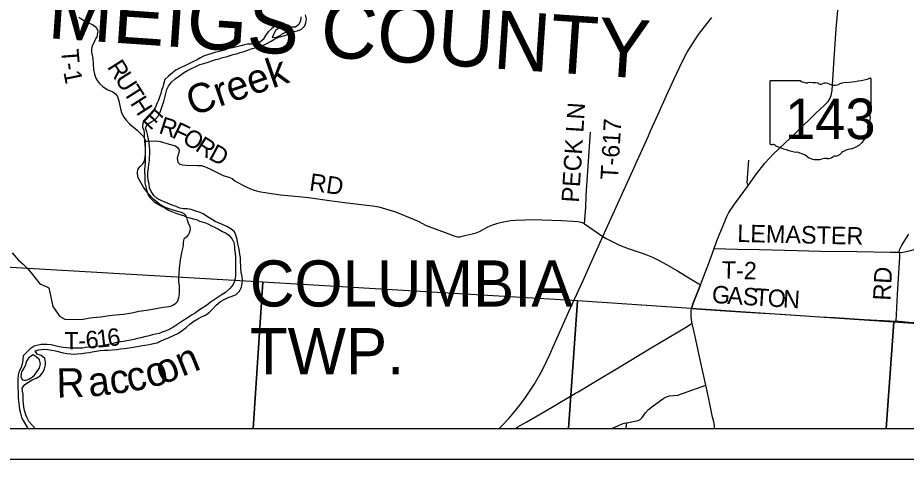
# Model space of a CAD drawing. Extents: x 0 to 34, y 0 to 22.
# Drawn here: x 4.418 to 7.302, y 14 to 15.435 of the extents above; entities that cross this region are included whole.
import ezdxf

# ---------------------------------------------------------------- set-up
doc = ezdxf.new("R2010")
doc.units = 0
for name, color, linetype in [('GM_X_Corporation', 7, 'Continuous'), ('GM_X_County_Road', 7, 'Continuous'), ('GM_X_County_Text', 7, 'Continuous'), ('GM_X_Major_River', 7, 'Continuous'), ('GM_X_Major_River_Text', 7, 'Continuous'), ('GM_X_State_Location', 7, 'Continuous'), ('GM_X_State_Route', 7, 'Continuous'), ('GM_X_State_Shield', 7, 'Continuous'), ('GM_X_Township_Road', 7, 'Continuous'), ('GM_X_Township_Road_Text', 7, 'Continuous'), ('GM_X_Township_Text', 7, 'Continuous'), ('SH_Data', 7, 'Continuous')]:
    doc.layers.add(name, color=color, linetype=linetype)

msp = doc.modelspace()

# ---------------------------------------------------------------- linework, layer by layer
at = {"layer": 'GM_X_Corporation'}
for points in [[(4.1481, 14.1), (8.9, 14.1), (8.9, 15.3662), (8.5054, 15.3919), (7.8479, 15.4342), (7.082, 15.4841), (6.7558, 15.5053), (6.7389, 15.5063), (6.2987, 15.5286), (5.4088, 15.5882), (4.4836, 15.6492), (4.4152, 15.6505), (4.2922, 15.6568), (4.2674, 15.6579), (4.2558, 15.6584), (4.2352, 15.4905), (4.2113, 15.0848), (4.1846, 14.6877), (4.1741, 14.5315), (4.1604, 14.3288)], [(4.1538, 14.1), (5.1819, 14.1), (5.2132, 14.5759), (4.1896, 14.6347)], [(5.1819, 14.1), (6.2054, 14.1), (6.2355, 14.5152), (5.2132, 14.5759)], [(6.2054, 14.1), (7.2372, 14.1), (7.2616, 14.4454), (6.2355, 14.5152)], [(7.2372, 14.1), (8.2568, 14.1), (8.2775, 14.3752), (7.2616, 14.4454)]]:
    msp.add_lwpolyline(points, close=True, dxfattribs=at)
at = {"layer": 'GM_X_County_Road'}
for points in [[(6.07, 14.1218), (6.1511, 14.1685), (6.2289, 14.2147), (6.2374, 14.2193), (6.2996, 14.2571), (6.3617, 14.2938), (6.4745, 14.3616), (6.5914, 14.4312), (6.6022, 14.4387), (6.6074, 14.4407)], [(6.0341, 14.1), (6.0414, 14.1051), (6.0562, 14.1139), (6.07, 14.1218)]]:
    msp.add_lwpolyline(points, dxfattribs=at)
at = {"layer": 'GM_X_Major_River'}
for points in [[(5.337, 15.4377), (5.3359, 15.4245), (5.3303, 15.4127), (5.319, 15.404), (5.3053, 15.4043), (5.294, 15.4103), (5.2807, 15.4141), (5.2674, 15.414), (5.2557, 15.4091), (5.2421, 15.4003), (5.2312, 15.3889), (5.2225, 15.3771), (5.2149, 15.3642), (5.2028, 15.354), (5.1904, 15.3513), (5.1767, 15.3493), (5.1639, 15.3485), (5.154, 15.3466), (5.1423, 15.3435), (5.1291, 15.3405), (5.1151, 15.3374), (5.1026, 15.3347), (5.0909, 15.3305), (5.0803, 15.3274), (5.0674, 15.3236), (5.0576, 15.3217), (5.0212, 15.3095), (5.0107, 15.3049), (4.9997, 15.2984), (4.9857, 15.2919), (4.971, 15.2839), (4.96, 15.2786), (4.9445, 15.2717), (4.9313, 15.2641), (4.9203, 15.2557), (4.9074, 15.2447), (4.8957, 15.2337), (4.8908, 15.2189), (4.8882, 15.2094), (4.8848, 15.1995), (4.8822, 15.1889), (4.8788, 15.1794), (4.8743, 15.1672), (4.8702, 15.1578), (4.8645, 15.1441), (4.8577, 15.1323), (4.8479, 15.1186), (4.8351, 15.1065), (4.8237, 15.0932), (4.8226, 15.0795), (4.8268, 15.0693), (4.8276, 15.0594), (4.828, 15.0466), (4.8292, 15.0337), (4.8307, 15.0212), (4.8311, 15.0113), (4.8311, 14.9988), (4.8315, 14.9863), (4.8316, 14.9658), (4.8301, 14.951), (4.829, 14.9415), (4.8294, 14.9321), (4.8302, 14.9222), (4.8298, 14.9082), (4.8306, 14.8987), (4.8333, 14.8854), (4.8363, 14.8722), (4.8409, 14.8593), (4.8481, 14.8495), (4.8606, 14.8366), (4.8732, 14.8287), (4.8868, 14.8211), (4.8985, 14.8143), (4.9092, 14.8087), (4.9201, 14.8038), (4.9308, 14.7997), (4.9436, 14.7948), (4.9554, 14.7918), (4.9667, 14.7872), (4.9766, 14.7846), (4.9876, 14.7816), (4.9978, 14.7786), (5.0077, 14.7741), (5.0236, 14.7688), (5.0345, 14.7647), (5.0467, 14.759), (5.0569, 14.7538), (5.0694, 14.7474)], [(5.1213, 14.7395), (5.1095, 14.749), (5.097, 14.7558), (5.0849, 14.7614), (5.0584, 14.7727), (5.0463, 14.7806), (5.0334, 14.7882), (5.0201, 14.7973), (5.0102, 14.8014), (4.9962, 14.8063), (4.9807, 14.8112), (4.9674, 14.8134), (4.9557, 14.8138), (4.9443, 14.8156), (4.9322, 14.8209), (4.9193, 14.8254), (4.9065, 14.8307), (4.8928, 14.8367), (4.8833, 14.8408), (4.8708, 14.8476), (4.8591, 14.8567), (4.8503, 14.8699), (4.8458, 14.8817), (4.8439, 14.8946), (4.8408, 14.9067), (4.8396, 14.9196), (4.84, 14.9313), (4.8419, 14.9465), (4.8433, 14.9575), (4.8452, 14.9708), (4.8456, 14.9821), (4.8463, 14.9928), (4.8466, 15.003), (4.8459, 15.0159), (4.8447, 15.0288), (4.8401, 15.0515), (4.8367, 15.0644), (4.8329, 15.0769), (4.8389, 15.0894), (4.851, 15.0963), (4.8627, 15.1031), (4.8737, 15.1153), (4.8804, 15.1282), (4.8838, 15.1377), (4.888, 15.1506), (4.8917, 15.1624), (4.8981, 15.1882), (4.9015, 15.2014), (4.9071, 15.2125), (4.9166, 15.225), (4.9287, 15.236), (4.9423, 15.2459), (4.9555, 15.2554), (4.9687, 15.2631), (4.9823, 15.2703), (4.9963, 15.2768), (5.0088, 15.2825), (5.0217, 15.2863), (5.036, 15.2905), (5.0474, 15.2947), (5.061, 15.299), (5.0712, 15.3016), (5.0826, 15.3051), (5.0947, 15.3078), (5.1045, 15.3105), (5.1166, 15.315), (5.1276, 15.3177), (5.1401, 15.3215), (5.1526, 15.325), (5.1647, 15.3292), (5.176, 15.3334), (5.1881, 15.3369), (5.2006, 15.3411), (5.215, 15.3453), (5.2267, 15.3506), (5.2403, 15.3582), (5.2524, 15.3662), (5.2649, 15.3712), (5.277, 15.3746), (5.2883, 15.3785), (5.3012, 15.3838), (5.3137, 15.3899), (5.3258, 15.3922), (5.3387, 15.3972), (5.3492, 15.4086), (5.353, 15.4181), (5.3549, 15.4314), (5.3522, 15.4439)], [(5.2974, 15.3952), (5.2906, 15.3974), (5.2822, 15.4001), (5.2747, 15.4019), (5.2686, 15.4015), (5.2622, 15.3989), (5.2558, 15.3939), (5.2509, 15.3863), (5.2478, 15.3802), (5.2433, 15.37)], [(5.2433, 15.37), (5.2577, 15.3712), (5.2645, 15.3746), (5.2713, 15.3784), (5.2777, 15.3834), (5.2838, 15.386), (5.2883, 15.3883), (5.2932, 15.3906), (5.2974, 15.3952)], [(5.0694, 14.7474), (5.0823, 14.7406), (5.094, 14.7342), (5.1035, 14.7281), (5.1142, 14.7153), (5.1187, 14.7039), (5.121, 14.691), (5.1218, 14.6815), (5.123, 14.6694), (5.1241, 14.6558), (5.1245, 14.6448), (5.1249, 14.6311), (5.125, 14.5955), (5.1224, 14.5811), (5.1167, 14.5682), (5.1062, 14.5549), (5.0922, 14.5423), (5.0816, 14.5358), (5.0555, 14.5183), (5.0427, 14.5092), (5.0302, 14.4993), (5.0166, 14.4905), (5.0049, 14.4829), (4.9935, 14.4742), (4.9822, 14.4677), (4.9675, 14.4586), (4.9535, 14.4498), (4.9436, 14.443), (4.9312, 14.4346), (4.9213, 14.4285), (4.9066, 14.4209), (4.8964, 14.4163), (4.8862, 14.4128), (4.8763, 14.4083), (4.865, 14.4063), (4.8548, 14.404), (4.84, 14.3998), (4.829, 14.3975), (4.8169, 14.3948), (4.8063, 14.3925), (4.795, 14.3895), (4.7844, 14.3872), (4.7723, 14.3845), (4.7609, 14.3822), (4.7511, 14.381), (4.7382, 14.3791), (4.7273, 14.3764), (4.7114, 14.3725), (4.7008, 14.3702), (4.6909, 14.3687), (4.6803, 14.3671), (4.6667, 14.366), (4.6527, 14.3644), (4.6376, 14.3636), (4.6277, 14.3613), (4.6141, 14.3605), (4.6016, 14.3605), (4.5884, 14.3608), (4.5755, 14.3615), (4.5653, 14.3626), (4.5524, 14.3656), (4.5391, 14.3686), (4.5263, 14.3716), (4.5134, 14.3727), (4.4937, 14.3727), (4.4835, 14.3707), (4.4706, 14.3677), (4.4578, 14.3593), (4.4472, 14.3479), (4.4351, 14.3365), (4.4336, 14.3225), (4.4321, 14.3088), (4.4291, 14.2986), (4.422, 14.2857), (4.4186, 14.2731), (4.4179, 14.2606), (4.4183, 14.2511), (4.4183, 14.2295), (4.4187, 14.2182), (4.4195, 14.2087), (4.4195, 14.1992), (4.4199, 14.1897), (4.4218, 14.1731), (4.4234, 14.1617), (4.4261, 14.1496), (4.4303, 14.1359), (4.4348, 14.1261), (4.4432, 14.1125), (4.4489, 14.1022), (4.4506, 14.1)], [(4.4747, 14.1), (4.4746, 14.1), (4.4651, 14.1091), (4.4549, 14.1212), (4.4477, 14.1345), (4.4439, 14.1447), (4.4393, 14.1587), (4.4378, 14.1693), (4.4362, 14.1811), (4.4354, 14.1905), (4.4354, 14.2106), (4.4335, 14.2212), (4.4316, 14.2311), (4.4406, 14.2425), (4.4527, 14.2509), (4.4648, 14.2577), (4.4777, 14.2631), (4.4901, 14.2714), (4.5, 14.2844), (4.5045, 14.2939), (4.5075, 14.3067), (4.5082, 14.317), (4.5055, 14.3276), (4.4938, 14.337), (4.4809, 14.3412), (4.4744, 14.3518), (4.4866, 14.356), (4.5009, 14.3572), (4.5157, 14.3561), (4.5282, 14.3546), (4.5399, 14.3523), (4.5649, 14.3463), (4.5771, 14.3441), (4.5892, 14.343), (4.6001, 14.3419), (4.6107, 14.3427), (4.6255, 14.3435), (4.6387, 14.3462), (4.6497, 14.3473), (4.6596, 14.3485), (4.6717, 14.3512), (4.6853, 14.3531), (4.6982, 14.3543), (4.7114, 14.3547), (4.725, 14.3551), (4.7379, 14.3567), (4.7511, 14.3586), (4.7636, 14.3598), (4.7788, 14.3621), (4.792, 14.364), (4.8053, 14.3664), (4.8159, 14.3687), (4.8446, 14.3733), (4.8579, 14.376), (4.8707, 14.3783), (4.8809, 14.3836), (4.8949, 14.3897), (4.9048, 14.3939), (4.9252, 14.4031), (4.9392, 14.41), (4.952, 14.4183), (4.9641, 14.4282), (4.9762, 14.4389), (4.9891, 14.4484), (5.0027, 14.4568), (5.0144, 14.4629), (5.0272, 14.4682), (5.0401, 14.4781), (5.0514, 14.4887), (5.062, 14.5009), (5.0764, 14.5123), (5.0881, 14.5196), (5.1013, 14.5253), (5.1138, 14.5299), (5.127, 14.5352), (5.1376, 14.5459), (5.1444, 14.5588), (5.1466, 14.5717), (5.147, 14.5811), (5.1458, 14.5937), (5.1428, 14.6077), (5.1424, 14.6206), (5.142, 14.63), (5.1408, 14.6403), (5.1404, 14.6554), (5.1392, 14.6657), (5.1377, 14.6759), (5.1358, 14.6869), (5.1327, 14.6998), (5.1301, 14.7145), (5.1262, 14.7282), (5.1213, 14.7395)], [(4.4673, 14.3396), (4.459, 14.3343), (4.4541, 14.329), (4.4503, 14.3248), (4.4458, 14.3187), (4.4439, 14.3115), (4.4424, 14.3058), (4.4379, 14.2959), (4.4303, 14.2842), (4.4284, 14.2773), (4.4277, 14.2682), (4.433, 14.2576)], [(4.433, 14.2576), (4.4379, 14.2565), (4.4444, 14.2573), (4.4478, 14.2581), (4.4531, 14.26), (4.4595, 14.2634), (4.4659, 14.268), (4.472, 14.2729), (4.4791, 14.2839), (4.4852, 14.2915), (4.4886, 14.2968), (4.4908, 14.3052), (4.4912, 14.3097), (4.4885, 14.323), (4.4862, 14.3253), (4.4779, 14.3328), (4.4673, 14.3396)]]:
    msp.add_lwpolyline(points, dxfattribs=at)
at = {"layer": 'GM_X_State_Route'}
for points in [[(6.7476, 14.8327), (6.7629, 14.8542), (6.7898, 14.8906), (6.8166, 14.9278), (6.8432, 14.9619), (6.8591, 14.9796), (6.8687, 14.9898), (6.9461, 15.0631), (7.0087, 15.1251), (7.0358, 15.1494), (7.0486, 15.1622), (7.0541, 15.1711), (7.0585, 15.1816), (7.0614, 15.1978), (7.0661, 15.269), (7.075, 15.3988), (7.0822, 15.4835)], [(5.9804, 14.1), (5.9868, 14.1059), (6.0116, 14.1319), (6.0284, 14.1515), (6.0478, 14.1752), (6.0665, 14.2006), (6.0945, 14.2428), (6.1109, 14.2714), (6.1231, 14.2951), (6.1436, 14.3381), (6.1599, 14.3752), (6.2073, 14.4799), (6.2193, 14.5056), (6.2529, 14.581), (6.2781, 14.6369), (6.317, 14.7235), (6.3386, 14.7712), (6.4078, 14.9242), (6.4654, 15.0513), (6.4725, 15.067), (6.497, 15.1215), (6.5242, 15.1824), (6.5487, 15.2367), (6.5758, 15.2937), (6.5915, 15.3226), (6.6079, 15.3497), (6.6281, 15.3803), (6.643, 15.3998), (6.6546, 15.4153), (6.671, 15.4354)], [(6.6348, 14.5669), (6.6615, 14.6369), (6.679, 14.6849), (6.6879, 14.7099), (6.7154, 14.7784), (6.7197, 14.7892), (6.7267, 14.8014), (6.7424, 14.8253), (6.7476, 14.8327)], [(6.6057, 14.4895), (6.6111, 14.5072), (6.6325, 14.5615), (6.6348, 14.5669)], [(6.6801, 14.1), (6.6797, 14.1091), (6.6778, 14.1213), (6.6738, 14.1372), (6.6611, 14.1966), (6.6515, 14.2403), (6.6354, 14.3134), (6.6166, 14.3991), (6.6074, 14.4407), (6.6057, 14.4527), (6.6041, 14.4649), (6.6041, 14.4748), (6.6043, 14.4822), (6.6057, 14.4895)]]:
    msp.add_lwpolyline(points, dxfattribs=at)
at = {"layer": 'GM_X_State_Shield'}
for p, q in [((7.1888, 15.13), (7.1888, 15.2347)), ((6.8592, 15.2263), (6.8592, 15.0262)), ((6.959, 15.2297), (6.8625, 15.2297)), ((7.1888, 15.13), (7.1888, 15.13))]:
    msp.add_line(p, q, dxfattribs=at)
for centre, major_axis, start_param, end_param in [((7.0714, 15.5026), (0.3495, 0), 4.814394, 5.042369), ((7.1851, 15.2351), (0.00367, 0), 6.141152, 7.989035), ((6.863, 15.2267), (0.00382, 0), 1.712693, 3.28349), ((6.982, 15.253), (0.037, 0), 4.042523, 4.731795), ((6.9942, 15.1174), (0.133, 0), 1.404758, 1.657858), ((7.0244, 15.2278), (0.0107, 0), 3.836095, 5.185415), ((7.0401, 15.2046), (0.0222, 0), 0.950623, 2.079405), ((7.0688, 15.2364), (0.0267, 0), 4.081561, 5.145723), ((7.116, 15.1686), (0.0703, 0), 1.699011, 2.107814), ((7.188, 15.1223), (0.00568, 0), 1.883978, 3.671073), ((7.1518, 15.1091), (0.0341, 0), 5.934695, 6.695948), ((7.1849, 15.1296), (0.00393, 0), 5.05454, 6.418171), ((7.2019, 15.0862), (0.0248, 0), 2.387724, 3.262537), ((7.091, 15.0729), (0.0874, 0), 5.101752, 6.440018), ((6.863, 15.0257), (0.00385, 0), 3.00124, 4.508301), ((6.8636, 15.0462), (0.0294, 0), 4.665946, 4.897461), ((6.8696, 15.0146), (0.0106, 0), 0.519207, 1.627899), ((7.0034, 15.1944), (0.2524, 0), 4.195997, 4.488961), ((7.1278, 14.97), (0.0479, 0), 1.647645, 2.488434), ((6.9282, 14.9363), (0.079, 0), 0.823519, 1.323587), ((7.0136, 15.0136), (0.0501, 0), 4.026481, 4.996735), ((7.0426, 14.9444), (0.0412, 0), 1.495662, 1.94098), ((7.0462, 14.9987), (0.0267, 0), 4.691044, 5.507374), ((7.0704, 14.9793), (0.00752, 0), 1.147584, 2.315152), ((7.0672, 15.0068), (0.0282, 0), 4.937069, 5.64225)]:
    msp.add_ellipse(centre, major_axis=major_axis, ratio=0.8, start_param=start_param, end_param=end_param, dxfattribs=at)
at = {"layer": 'GM_X_Township_Road'}
msp.add_line((6.2573, 14.7653), (6.317, 14.7235), dxfattribs=at)
for points in [[(4.6157, 15.4371), (4.6259, 15.4299), (4.6346, 15.4242), (4.6443, 15.4193), (4.6602, 15.4129), (4.6695, 15.4062), (4.6745, 15.4), (4.6775, 15.3926), (4.6769, 15.3856), (4.6755, 15.3783), (4.6739, 15.3732), (4.6706, 15.366), (4.6663, 15.3578), (4.66, 15.3455), (4.6579, 15.3388), (4.6566, 15.332), (4.6568, 15.3241), (4.6586, 15.3174), (4.6619, 15.3019), (4.663, 15.2854), (4.6635, 15.2669), (4.6669, 15.2519), (4.6716, 15.2379), (4.6762, 15.2295), (4.6831, 15.2206), (4.6934, 15.2114), (4.7082, 15.2017), (4.7259, 15.194), (4.735, 15.1872), (4.7412, 15.1788), (4.744, 15.1715), (4.7458, 15.1643), (4.7481, 15.1537), (4.752, 15.1348), (4.7541, 15.1267), (4.7578, 15.1189), (4.7621, 15.1115), (4.7695, 15.1021), (4.7804, 15.0903), (4.8053, 15.0689), (4.8164, 15.0585), (4.8246, 15.0502), (4.8274, 15.0467), (4.8288, 15.0426), (4.8325, 15.0341), (4.8398, 15.0339), (4.868, 15.0345), (4.8795, 15.0326), (4.9091, 15.0243), (4.9299, 15.0183), (4.9367, 15.0135), (4.9401, 15.0078), (4.9414, 15.0019), (4.9411, 14.9968), (4.9387, 14.9891), (4.9353, 14.9781), (4.9358, 14.9703), (4.9376, 14.9655), (4.9404, 14.9621), (4.9444, 14.9593), (4.9523, 14.9566), (4.9636, 14.9556), (5.0024, 14.9549), (5.014, 14.9546), (5.0245, 14.9515), (5.0439, 14.943), (5.0609, 14.9339), (5.0739, 14.9273), (5.0848, 14.9226), (5.1034, 14.9168), (5.1136, 14.9118), (5.1229, 14.9045), (5.1466, 14.8917), (5.1616, 14.8846), (5.173, 14.879), (5.1857, 14.8742), (5.2003, 14.8702), (5.2269, 14.8655), (5.2708, 14.8597), (5.3062, 14.8557), (5.3613, 14.8509), (5.4293, 14.8406), (5.479, 14.8341), (5.5515, 14.8261), (5.5709, 14.8237), (5.5904, 14.82), (5.6121, 14.8137), (5.6445, 14.8039), (5.6733, 14.7924), (5.7182, 14.7732), (5.744, 14.7597), (5.8058, 14.7371), (5.8364, 14.7249), (5.8454, 14.723), (5.8516, 14.7229), (5.874, 14.7284), (5.8927, 14.732), (5.906, 14.7354), (5.9173, 14.7406), (5.9436, 14.755), (5.9597, 14.762), (5.9759, 14.7676), (5.9953, 14.7719), (6.0187, 14.7754), (6.034, 14.7767), (6.0649, 14.7784), (6.0864, 14.7793), (6.1837, 14.7757), (6.2197, 14.7739), (6.236, 14.7729), (6.2419, 14.7716), (6.2464, 14.7705), (6.2501, 14.7688), (6.2573, 14.7653)], [(6.2573, 14.7653), (6.2616, 14.8192), (6.2637, 14.8573), (6.2702, 14.9529), (6.2769, 15.0629)], [(4.5489, 14.4713), (4.5531, 14.4649), (4.5704, 14.4554), (4.6245, 14.4544), (4.6519, 14.459), (4.6729, 14.4616), (4.6874, 14.4624), (4.708, 14.4659), (4.7241, 14.4682), (4.7476, 14.4699), (4.7608, 14.4712), (4.7882, 14.4758), (4.8106, 14.4807), (4.8355, 14.4842), (4.8555, 14.4874), (4.8894, 14.4938), (4.9088, 14.4966), (4.9169, 14.4987), (4.9233, 14.5017), (4.9311, 14.5067), (4.9358, 14.5125), (4.939, 14.519), (4.9409, 14.525), (4.9425, 14.537), (4.9432, 14.5512), (4.9425, 14.5642), (4.9409, 14.5761), (4.9402, 14.5883), (4.9413, 14.6043), (4.9427, 14.6197), (4.9461, 14.6476), (4.9507, 14.6709), (4.9508, 14.6716), (4.9544, 14.6893), (4.9554, 14.6981), (4.9558, 14.7046), (4.9567, 14.7106), (4.9575, 14.7149), (4.9595, 14.7182), (4.9635, 14.7214), (4.9685, 14.7248), (4.9718, 14.7294), (4.9756, 14.7359), (4.9778, 14.7435), (4.9786, 14.7488), (4.9775, 14.7553), (4.9724, 14.7668), (4.9687, 14.7774), (4.9669, 14.7855), (4.9635, 14.7919), (4.9581, 14.7973), (4.9491, 14.8021), (4.9258, 14.8083), (4.8993, 14.8171), (4.8791, 14.8282), (4.8599, 14.8441), (4.8415, 14.8632), (4.8258, 14.884), (4.8127, 14.9074), (4.809, 14.9149), (4.8074, 14.922), (4.8064, 14.928), (4.8069, 14.9337), (4.808, 14.9404), (4.811, 14.9457), (4.8149, 14.9514), (4.8235, 14.9605), (4.8279, 14.9667), (4.8295, 14.9718), (4.8309, 14.9799), (4.832, 14.9937), (4.8327, 15.0084), (4.8325, 15.0218), (4.8325, 15.0341)], [(6.7898, 14.8906), (6.7875, 14.8952), (6.7862, 14.8993), (6.7885, 14.9284), (6.7908, 14.9716)], [(7.2792, 14.6724), (7.2862, 14.6713), (7.3117, 14.6775), (7.3412, 14.6846), (7.3507, 14.687), (7.3594, 14.6875), (7.3791, 14.6862), (7.3894, 14.686), (7.3967, 14.6864), (7.404, 14.6881), (7.4099, 14.6909), (7.4202, 14.696), (7.4479, 14.7122), (7.4852, 14.7336), (7.4989, 14.7425), (7.5078, 14.7464), (7.5172, 14.7493)], [(6.317, 14.7235), (6.328, 14.7176), (6.3624, 14.6995), (6.377, 14.6931), (6.3996, 14.6851), (6.426, 14.6762), (6.451, 14.6679), (6.4782, 14.6566), (6.5001, 14.646), (6.522, 14.6336), (6.5592, 14.6124), (6.5968, 14.5892), (6.6348, 14.5669)], [(7.2792, 14.6724), (7.2809, 14.6806), (7.2885, 14.6953), (7.3105, 14.7317)], [(6.679, 14.6849), (6.7547, 14.6828), (6.8261, 14.6816), (6.9481, 14.6788), (7.0241, 14.6763), (7.1415, 14.6747), (7.2516, 14.6728), (7.2792, 14.6724)], [(4.3992, 14.671), (4.4188, 14.6484), (4.4347, 14.6344), (4.4512, 14.6179), (4.4699, 14.5948), (4.4897, 14.5699), (4.5095, 14.5615), (4.519, 14.5573), (4.5319, 14.4967), (4.5489, 14.4713)], [(6.6057, 14.4895), (6.6817, 14.4843), (6.7812, 14.4775), (6.8968, 14.4711), (7.022, 14.4632), (7.0692, 14.4603), (7.1653, 14.4541), (7.2692, 14.4482), (7.2741, 14.5354), (7.2812, 14.6578), (7.2812, 14.6671), (7.2792, 14.6724)], [(6.6348, 14.5669), (6.6325, 14.5615), (6.6111, 14.5072), (6.6057, 14.4895)], [(7.5005, 14.411), (7.4904, 14.4292), (7.4808, 14.4349), (7.4701, 14.4414), (7.4665, 14.4442), (7.4643, 14.444), (7.4593, 14.4416), (7.4287, 14.4384), (7.3731, 14.4416), (7.3103, 14.4448), (7.2692, 14.4482)], [(6.3938, 14.118), (6.3948, 14.1182), (6.4323, 14.1258), (6.4385, 14.1286), (6.4446, 14.1353), (6.456, 14.1505), (6.4651, 14.1618), (6.4803, 14.1732), (6.5154, 14.1989), (6.5235, 14.2027), (6.5339, 14.2055), (6.5472, 14.207), (6.5605, 14.2079), (6.6515, 14.2403)], [(6.3441, 14.1), (6.3492, 14.1015), (6.3663, 14.1082), (6.3801, 14.1148), (6.3881, 14.1167), (6.3938, 14.118)], [(6.3931, 14.1), (6.3934, 14.103), (6.3948, 14.1182)]]:
    msp.add_lwpolyline(points, dxfattribs=at)
at = {"layer": 'SH_Data'}
for p, q in [((4.1481, 14.1), (8.9, 14.1)), ((2, 14), (9, 14))]:
    msp.add_line(p, q, dxfattribs=at)

# ---------------------------------------------------------------- texts
at = {"layer": 'GM_X_County_Text'}
msp.add_text('MEIGS COUNTY', height=0.189394, rotation=356.1113, dxfattribs=at).set_placement((4.512, 15.3686))
at = {"layer": 'GM_X_Major_River_Text'}
for s, height, rotation, p in [('Creek', 0.0947, 19.0988, (4.9848, 15.1149)), ('on', 0.09469, 22.0989, (4.8864, 14.241)), ('co', 0.0947, 13.1008, (4.781, 14.2174)), ('R', 0.0947, 1.1029, (4.5442, 14.2003)), ('ac', 0.0947, 7.102, (4.6511, 14.2023))]:
    msp.add_text(s, height=height, rotation=rotation, dxfattribs=at).set_placement(p)
at = {"layer": 'GM_X_State_Location'}
msp.add_text('143', height=0.000189, rotation=0, dxfattribs=at).set_placement((6.9534, 15.0992))
for s in ['s', 'r']:
    msp.add_text(s, height=0.000189, dxfattribs=at).set_placement((7.0203, 15.1129))
at = {"layer": 'GM_X_State_Shield'}
msp.add_text('143', height=0.13184, dxfattribs=at).set_placement((6.9087, 15.0403))
at = {"layer": 'GM_X_Township_Road_Text'}
for s, height, rotation, p in [('T', 0.0568, 274.6248, (4.5582, 15.331)), ('R', 0.0568, 302.319, (4.7065, 15.275)), ('1', 0.0568, 281.6376, (4.5655, 15.258)), ('-', 0.0568, 276.9198, (4.5619, 15.2862)), ('U', 0.0568, 302.3208, (4.7315, 15.2356)), ('T', 0.0568, 302.3207, (4.7582, 15.1933)), ('H', 0.0568, 302.7166, (4.7812, 15.157)), ('PECK LN', 0.05682, 86.3714, (6.2395, 14.833)), ('E', 0.0568, 317.0494, (4.8181, 15.1031)), ('R', 0.0568, 342.3324, (4.8727, 15.0604)), ('F', 0.0568, 334.5123, (4.9152, 15.047)), ('T-617', 0.05682, 86.6338, (6.366, 14.9069)), ('O', 0.0568, 328.0894, (4.9484, 15.0313)), ('R', 0.0568, 327.0439, (4.9906, 15.005)), ('D', 0.0568, 331.5761, (5.0339, 14.9771)), ('RD', 0.05682, 351.7984, (5.362, 14.8735)), ('LEMASTER', 0.05682, 358.7066, (6.7533, 14.7062)), ('T-2', 0.05682, 358.5687, (6.7026, 14.5869)), ('RD', 0.05682, 87.0658, (7.2511, 14.5145)), ('G', 0.0568, 355.6865, (6.6698, 14.5085)), ('A', 0.0568, 356.4682, (6.7205, 14.5047)), ('S', 0.0568, 356.4771, (6.7704, 14.5016)), ('T', 0.0568, 356.4815, (6.8087, 14.4993)), ('O', 0.0568, 356.4789, (6.8511, 14.4967)), ('N', 0.0568, 356.4814, (6.901, 14.4936)), ('6', 0.0568, 6.8816, (4.7117, 14.366)), ('T', 0.0568, 359.9957, (4.5688, 14.3569)), ('6', 0.0568, 5.1433, (4.6402, 14.3587)), ('1', 0.0568, 6.5284, (4.6765, 14.362)), ('-', 0.0568, 3.7069, (4.6153, 14.3571))]:
    msp.add_text(s, height=height, rotation=rotation, dxfattribs=at).set_placement(p)
at = {"layer": 'GM_X_Township_Text'}
for s, p in [('COLUMBIA', (5.1714, 14.4962)), ('TWP.', (5.1714, 14.2762))]:
    msp.add_text(s, height=0.15, rotation=0, dxfattribs=at).set_placement(p)

doc.saveas('drawing.dxf')
